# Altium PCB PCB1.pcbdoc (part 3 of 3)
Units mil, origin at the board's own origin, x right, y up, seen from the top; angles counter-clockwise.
Board outline 1393.7 x 1462.72 mil, 2 copper layers (Top Layer, Bottom Layer), stack 62.206 mil thick; 10 components, 35 nets, 86 pads, 11 vias.
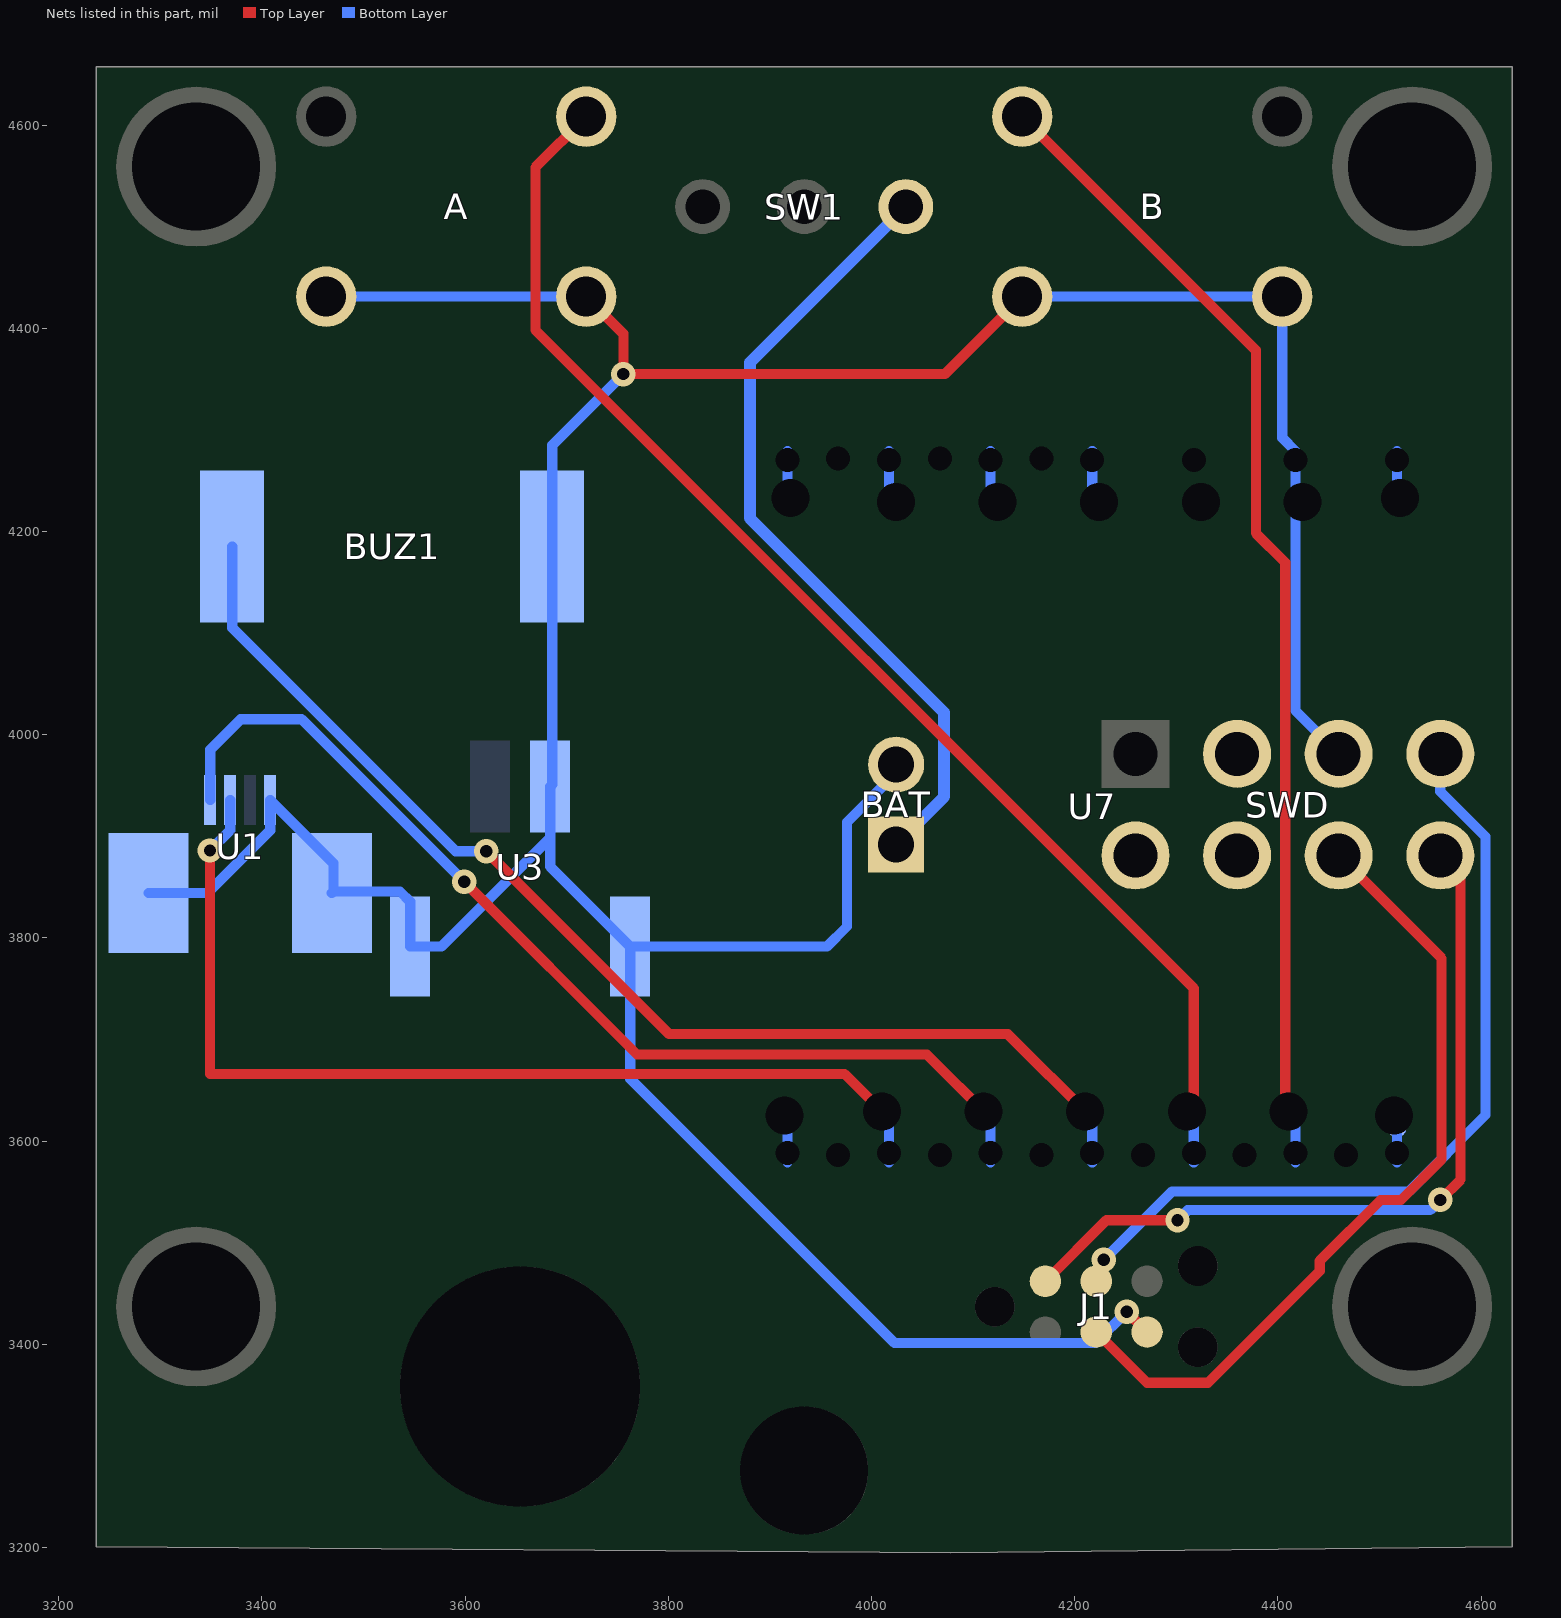
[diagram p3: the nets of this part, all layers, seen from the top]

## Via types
v1: diameter 24.02, hole 12, Top Layer to Bottom Layer, 11 vias

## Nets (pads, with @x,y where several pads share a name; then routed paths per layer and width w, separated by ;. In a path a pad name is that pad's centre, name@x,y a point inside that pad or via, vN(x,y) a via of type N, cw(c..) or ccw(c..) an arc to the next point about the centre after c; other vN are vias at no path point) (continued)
GND: A.21 A.22 B.21 B.22 BAT.2 BUZ1.1 J1.5 SWD.5 U1.1 U1.5 U1.6 U3.1 U3.3 U3.4 U7.13 | length 3893.7
  Top Layer w10: A.22@3719.21,4431.1 3755.74,4394.57 v1(3755.74,4354.84) 4072.08,4354.84 B.21@4148.35,4431.1 ; v1(4251.18,3432.01) J1.5@4271.18,3412.01
  Bottom Layer w10: U1.5@3288.5,3844 3346.26,3844 3408.19,3905.92 U1.1@3408.19,3935.53 3470.37,3873.35 U1.6@3470.37,3845.55 ; A.21@3463.31,4431.1 A.22@3719.21,4431.1 ; U1.6@3468.82,3844 U1.6@3470.37,3845.55 ; v1(3755.74,4354.84) 3685.74,4284.84 BUZ1.1@3685.74,4185.03 3685.74,3950.79 U3.1@3683.78,3948.82 3683.77,3898.54 ; BAT.2@4024.33,3970.47 4024.33,3962.38 3975.83,3913.88 3975.83,3811.18 3955.98,3791.34 U3.4@3762.52,3791.34 ; B.21@4148.35,4431.1 B.22@4404.25,4431.1 4404.25,4292.12 4417.24,4279.13 4417.24,4236.02 4417.24,4023.7 SWD.5@4459.84,3981.1 ; v1(4251.18,3432.01) 4220.51,3401.34 4022.51,3401.34 3762.51,3661.34 U3.4@3762.52,3791.34 ; U1.6@3470.37,3845.55 3535.99,3845.55 3545.99,3835.55 U3.3@3545.99,3791.34 3576.57,3791.34 3683.77,3898.54 ; 3683.77,3898.54 3683.77,3870.08 U3.4@3762.52,3791.34
P0.00_D19: U7.15
P0.01_D20: U7.16
P0.02_D21: U7.17
P0.03_D22: U7.18
P0.04_D23: U7.19
P0.05_D24: U7.20
P1.00_A0_D0: U7.1 | length 43.1
  Bottom Layer w10: 4517.24,3579.13 U7.1@4517.24,3613.07 U7.1@4517.24,3622.24
P1.03_SDA_A7_D4: U1.4 U7.5 | length 1036
  Top Layer w10: v1(3599.13,3855.14) 3769.13,3685.14 4054.35,3685.14 U7.5@4117.24,3622.24
  Bottom Layer w10: U1.4@3349.13,3935.53 3349.13,3985.14 3379.13,4015.14 3439.13,4015.14 v1(3599.13,3855.14) ; 4117.24,3579.13 U7.5@4117.24,3622.24
P1.04_SCK_A6_D8: U7.9 | length 43.1
  Bottom Layer w10: U7.9@4017.24,4236.02 4017.24,4279.13
P1.05_MISO_A5_D9: U7.10 | length 43.1
  Bottom Layer w10: U7.10@4117.24,4236.02 4117.24,4279.13
P1.06_MOSI_A4_D10: U7.11 | length 43.1
  Bottom Layer w10: U7.11@4217.24,4236.02 4217.24,4279.13
P1.07_SCL_A8_D5: U1.3 U7.6 | length 1007.5
  Top Layer w10: v1(3348.82,3885.92) 3348.82,3665.92 3973.56,3665.92 U7.6@4017.24,3622.24
  Bottom Layer w10: v1(3348.82,3885.92) 3368.82,3905.92 U1.3@3368.82,3935.53 ; 4017.24,3579.13 U7.6@4017.24,3622.24
P1.08_Tx_D6: U7.7
P1.08_TX_D6:  | length 43.1
  Bottom Layer w10: 3917.24,3579.13 3917.24,3622.24
P1.09_Rx_D7: U7.8
P1.09_RX_D7:  | length 43.1
  Bottom Layer w10: 3917.24,4236.02 3917.24,4279.13
P1.29_A3_D3: BUZ1.2 U7.4 | length 1169.4
  Top Layer w10: v1(3620.78,3885.23) 3800.78,3705.24 4134.25,3705.24 U7.4@4217.24,3622.24
  Bottom Layer w10: BUZ1.2@3370.78,4185.03 3370.78,4105.23 3590.78,3885.23 v1(3620.78,3885.23) ; 4217.24,3579.13 U7.4@4217.24,3622.24
P1.30_A2_D2: A.12 U7.3 | length 1318.3
  Top Layer w10: A.12@3719.21,4608.27 3669.21,4558.27 3669.21,4398.27 4317.24,3750.24 U7.3@4317.24,3622.24
  Bottom Layer w10: 4317.24,3579.13 U7.3@4317.24,3622.24
P1.31_A1_D1: B.11 U7.2 | length 1140.5
  Top Layer w10: B.11@4148.35,4608.27 4378.35,4378.27 4378.35,4198.27 4407.24,4169.38 4407.24,3632.24 U7.2@4417.24,3622.24
  Bottom Layer w10: 4417.24,3579.13 U7.2@4417.24,3622.24
P3.09_D25: U7.21
P3.10_D26: U7.22
P3.11_D27: U7.23
power_+5V: U7.14
POWER_+5V:  | length 43.1
  Bottom Layer w10: 4517.24,4236.02 4517.24,4279.13
RST: J1.3 SWD.6 | length 798.8
  Top Layer w10: J1.3@4221.18,3412.01 4271.18,3362.01 4331.18,3362.01 4441.18,3472.01 4441.18,3482.01 4501.18,3542.01 4521.18,3542.01 4561.18,3582.01 4561.18,3779.76 SWD.6@4459.84,3881.1
RST2: SWD.2
SWCLK: J1.4 SWD.7 | length 808.6
  Bottom Layer w10: v1(4228.66,3483.07) 4296.02,3550.43 4529.13,3550.43 4604.29,3625.59 4604.29,3899.51 4559.84,3943.96 SWD.7@4559.84,3981.1
SWCLK2: SWD.3
SWDIO: J1.2 SWD.8 | length 777.5
  Top Layer w10: J1.2@4171.18,3462.01 4231.18,3522.01 v1(4301.18,3522.01) ; v1(4559.84,3542.01) 4579.84,3562.01 4579.84,3861.1 SWD.8@4559.84,3881.1
  Bottom Layer w10: v1(4301.18,3522.01) 4311.18,3532.01 4549.84,3532.01 v1(4559.84,3542.01)
SWDIO2: SWD.4
VBAT: BAT.1 SW1.3 | length 790.4
  Bottom Layer w11.81: BAT.1@4024.33,3891.73 4071.57,3938.97 4071.57,4021.65 3880.23,4212.99 3880.23,4366.14 SW1.3@4033.78,4519.69
pads on no net: A.11 B.12 J1. J1.6 SW1.2

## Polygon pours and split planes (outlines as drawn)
GND on Top Layer (solid, remove dead copper, pour order 0): 3000,4803.07 3000,3000 4921.54,3000 4921.54,4803.07
GND on Bottom Layer (solid, remove dead copper, pour order 4): 3092.36,4736.81 3092.36,3092.36 4803.07,3092.36 4803.07,4736.81

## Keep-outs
Board Outline Layer:
  region: 3795.98,4031.5 3795.98,3791.1 4221.18,3791.1 4221.18,4031.5
  lines w10: 3236.93,3200.79 3236.93,4657.48 4630.63,4657.48 4630.63,4165.35 4630.63,4047.24 4630.63,3811.02 4630.63,3692.91 4630.63,3200.79 4078.23,3194.76 3236.93,3200.79

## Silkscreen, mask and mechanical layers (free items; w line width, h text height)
Top Silkscreen Layer:
  text "XIAO nRF54LM20A" at 4222.8,4102.32 h25.98
  text "SWCLK2" at 4397.48,4032.05 h26 r270
  text "SWCLK" at 4598.27,4017.99 h26 r270
  text "-" at 4082.24,4009.96 h120 r90
  text "3V3" at 4297.09,4003.94 h26 r270
  text "GND" at 4497.87,4001.93 h26 r270
  text "SWDIO2" at 4397.48,3925.63 h26 r270
  text "SWDIO" at 4596.26,3915.59 h26 r270
  text "RST2" at 4297.09,3911.57 h26 r270
  text "RST" at 4495.87,3899.53 h26 r270
  text "+" at 3985.87,3762.99 h120
  text "Claude Buddy v0.3" at 4240.87,3240.16 h39.37
Bottom Silkscreen Layer:
  text "XIAO nRF54LM20A" at 4447.68,4104.33 h25.98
